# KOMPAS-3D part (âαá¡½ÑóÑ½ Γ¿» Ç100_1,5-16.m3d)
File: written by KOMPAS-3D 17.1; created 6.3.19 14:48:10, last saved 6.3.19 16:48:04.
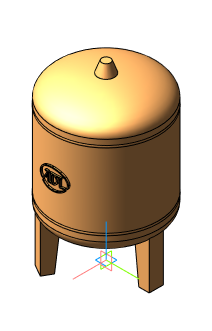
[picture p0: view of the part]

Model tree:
1. Операция без истории:1  (with: Сечение модели:1)

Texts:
  Гранлевел тип А100_1,5-16
  Гранлевел тип А150_1,5-16
  Гранлевел тип А220_1,5-16
  Гранлевел тип А350_1,5-16
  Гранлевел тип А500_1,5-16
  Гранлевел тип А700_1,5-16
  Гранлевел тип А900_1,5-16
  Гранлевел тип А1000_1,5-16
  Гранлевел тип А1400_1,5-16
  Точка начала. Х
  Точка начала. Y
  Точка начала. Z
